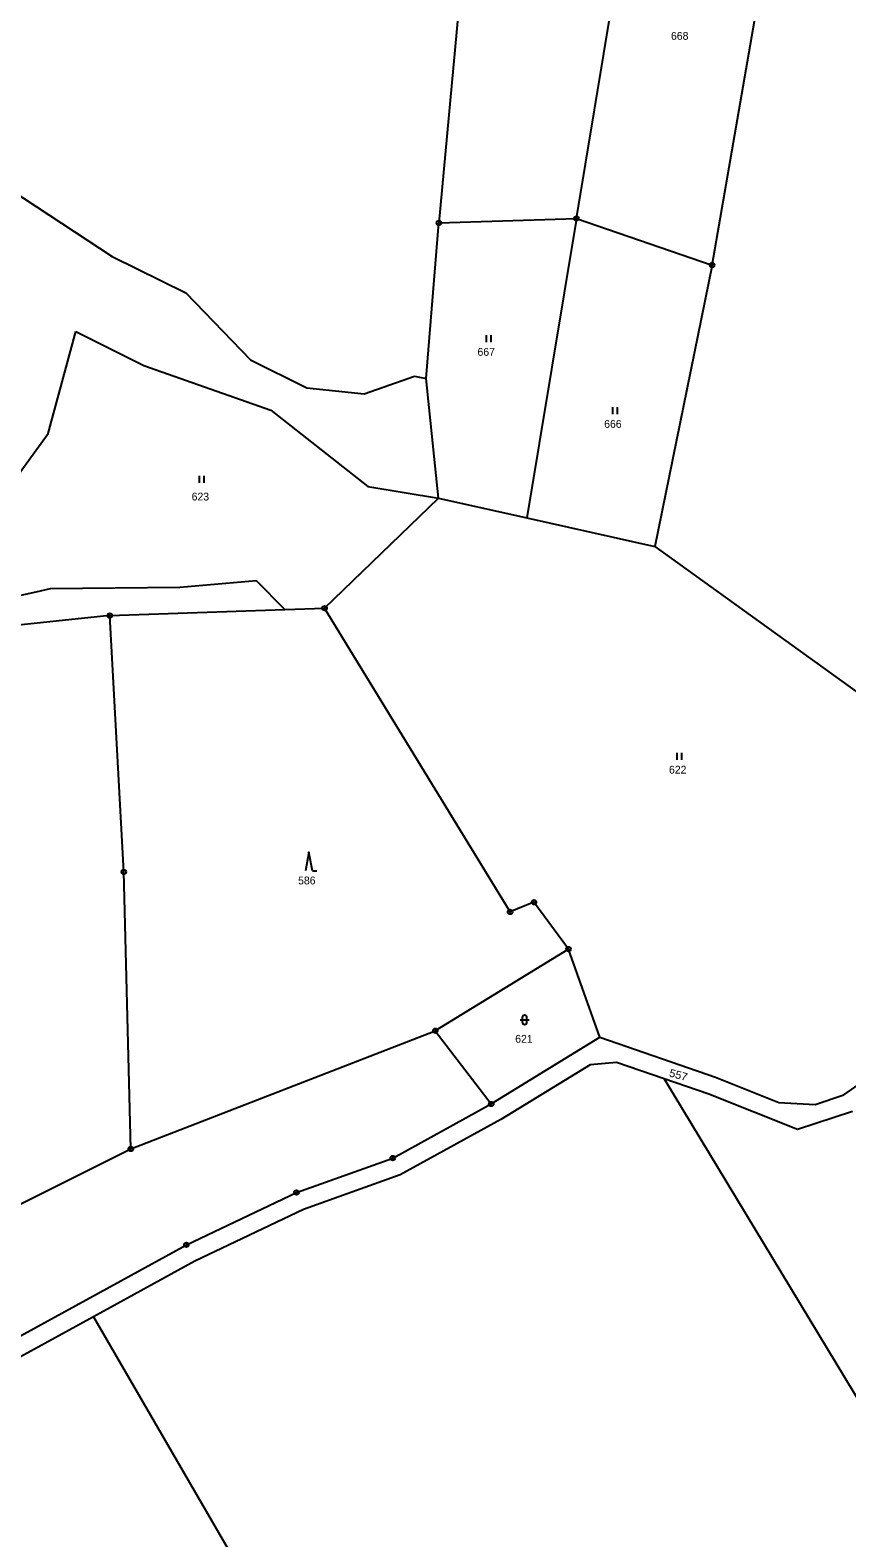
# Model space of a CAD drawing. Extents: x -719614 to -717765, y -1095834 to -1093862.
# Drawn here: x -718549.9 to -718372.3, y -1095029.2 to -1094701.4 of the extents above; entities that cross this region are included whole.
import ezdxf
from ezdxf.enums import TextEntityAlignment as Align

# ---------------------------------------------------------------- set-up
doc = ezdxf.new("R2010")
doc.units = 0
doc.header["$LTSCALE"] = 0.68
for name, color, linetype, lineweight in [('1', 7, 'Continuous', 25), ('3', 7, 'Continuous', 25), ('8', 7, 'Continuous', 25)]:
    doc.layers.add(name, color=color, linetype=linetype, lineweight=lineweight)
doc.layers.add('2', color=7, linetype='Continuous')

msp = doc.modelspace()

# ---------------------------------------------------------------- linework, layer by layer
at = {"layer": '1'}
for p, q in [((-718451.67, -1094641.63), (-718460.98, -1094743.29)), ((-718401.57, -1094752.45), (-718386.43, -1094665.2)), ((-718431.06, -1094742.32), (-718423.14, -1094694.58)), ((-718556.9, -1094734.3), (-718532.04, -1094750.61)), ((-718460.98, -1094743.29), (-718431.06, -1094742.32)), ((-718431.06, -1094742.32), (-718441.87, -1094807.45)), ((-718431.06, -1094742.32), (-718401.57, -1094752.45)), ((-718463.78, -1094777.11), (-718460.98, -1094743.29)), ((-718532.04, -1094750.61), (-718516.03, -1094758.47)), ((-718401.57, -1094752.45), (-718414, -1094813.69)), ((-718516.03, -1094758.47), (-718501.96, -1094773.06)), ((-718545.93, -1094789.06), (-718539.91, -1094766.88)), ((-718539.91, -1094766.88), (-718525.16, -1094774.33)), ((-718525.16, -1094774.33), (-718497.54, -1094783.98)), ((-718501.96, -1094773.06), (-718489.69, -1094779.16)), ((-718477.25, -1094780.47), (-718466.33, -1094776.59)), ((-718466.33, -1094776.59), (-718463.78, -1094777.11)), ((-718461.06, -1094803.16), (-718463.78, -1094777.11)), ((-718489.69, -1094779.16), (-718477.25, -1094780.47)), ((-718497.54, -1094783.98), (-718476.43, -1094800.59)), ((-718561.31, -1094810.12), (-718545.93, -1094789.06)), ((-718476.43, -1094800.59), (-718461.06, -1094803.16)), ((-718485.85, -1094827.06), (-718461.06, -1094803.16)), ((-718461.06, -1094803.16), (-718441.87, -1094807.45)), ((-718441.87, -1094807.45), (-718414, -1094813.69)), ((-718414, -1094813.69), (-718370.26, -1094845.2)), ((-718548.67, -1094823.59), (-718557.52, -1094825.53)), ((-718545.54, -1094822.9), (-718548.67, -1094823.59)), ((-718517.36, -1094822.59), (-718545.54, -1094822.9)), ((-718500.69, -1094821.11), (-718517.36, -1094822.59)), ((-718494.51, -1094827.36), (-718500.69, -1094821.11)), ((-718532.55, -1094828.68), (-718494.51, -1094827.36)), ((-718494.51, -1094827.36), (-718485.85, -1094827.06)), ((-718445.51, -1094893.13), (-718485.85, -1094827.06)), ((-718532.55, -1094828.68), (-718569.7, -1094832.59)), ((-718529.51, -1094884.42), (-718532.55, -1094828.68)), ((-718528, -1094944.67), (-718529.51, -1094884.42)), ((-718440.31, -1094891.02), (-718445.51, -1094893.13)), ((-718432.8, -1094901.2), (-718440.31, -1094891.02)), ((-718432.8, -1094901.2), (-718461.77, -1094918.96)), ((-718425.98, -1094920.36), (-718432.8, -1094901.2)), ((-718372.9, -1094932.91), (-718331.65, -1094903.88)), ((-718528, -1094944.67), (-718461.77, -1094918.96)), ((-718461.77, -1094918.96), (-718449.61, -1094934.89)), ((-718449.61, -1094934.89), (-718425.98, -1094920.36)), ((-718425.98, -1094920.36), (-718400.86, -1094929.03)), ((-718422.36, -1094925.84), (-718428.13, -1094926.38)), ((-718411.97, -1094929.43), (-718422.36, -1094925.84)), ((-718428.13, -1094926.38), (-718433.56, -1094929.72)), ((-718400.86, -1094929.03), (-718387.07, -1094934.54)), ((-718433.56, -1094929.72), (-718447.51, -1094938.3)), ((-718402.26, -1094932.78), (-718411.97, -1094929.43)), ((-718411.97, -1094929.43), (-718310.27, -1095097.96)), ((-718471.03, -1094946.65), (-718449.61, -1094934.89)), ((-718383.03, -1094940.46), (-718402.26, -1094932.78)), ((-718387.07, -1094934.54), (-718379.17, -1094934.98)), ((-718379.17, -1094934.98), (-718372.9, -1094932.91)), ((-718447.51, -1094938.3), (-718469.38, -1094950.31)), ((-718371.08, -1094936.52), (-718383.03, -1094940.46)), ((-718588.3, -1094974.71), (-718528, -1094944.67)), ((-718491.95, -1094954.14), (-718471.03, -1094946.65)), ((-718469.38, -1094950.31), (-718490.44, -1094957.85)), ((-718515.91, -1094965.53), (-718491.95, -1094954.14)), ((-718490.44, -1094957.85), (-718514.09, -1094969.09)), ((-718600.21, -1095011.66), (-718515.91, -1094965.53)), ((-718514.09, -1094969.09), (-718536.12, -1094981.15)), ((-718536.12, -1094981.15), (-718598.59, -1095015.34)), ((-718536.12, -1094981.15), (-718446.03, -1095136.65))]:
    msp.add_line(p, q, dxfattribs=at)
at = {"layer": '3'}
for p, q in [((-718450.651, -1094769.2), (-718450.651, -1094767.7)), ((-718449.65, -1094769.2), (-718449.65, -1094767.7)), ((-718423.131, -1094784.87), (-718423.131, -1094783.37)), ((-718422.13, -1094784.87), (-718422.13, -1094783.37)), ((-718513.031, -1094799.82), (-718513.031, -1094798.32)), ((-718512.03, -1094799.82), (-718512.03, -1094798.32)), ((-718409.171, -1094860.06), (-718409.171, -1094858.56)), ((-718408.17, -1094860.06), (-718408.17, -1094858.56)), ((-718488.5, -1094884.16), (-718487.504, -1094884.16)), ((-718442.851, -1094916.081), (-718442.851, -1094917.082)), ((-718441.849, -1094917.082), (-718441.849, -1094916.081)), ((-718443.351, -1094916.581), (-718441.349, -1094916.581))]:
    msp.add_line(p, q, dxfattribs=at)
msp.add_lwpolyline([(-718488.5, -1094884.16), (-718489.25, -1094880.16), (-718490, -1094884.16)], dxfattribs=at)
for centre, start, end in [((-718442.35, -1094916.0809), 0, 180), ((-718442.35, -1094917.0809), 180, 359.98789)]:
    msp.add_arc(centre, 0.5, start, end, dxfattribs=at)
at = {"layer": '8'}
for centre, radius in [((-718431.06, -1094742.3199), 0.5), ((-718431.06, -1094742.3199), 0.0303), ((-718460.98, -1094743.2899), 0.5), ((-718460.98, -1094743.2899), 0.0303), ((-718401.57, -1094752.4499), 0.5), ((-718401.57, -1094752.4499), 0.0303), ((-718485.85, -1094827.0599), 0.5), ((-718485.85, -1094827.0599), 0.0303), ((-718532.55, -1094828.6799), 0.5), ((-718532.55, -1094828.6799), 0.0303), ((-718529.51, -1094884.4199), 0.5), ((-718529.51, -1094884.4199), 0.0303), ((-718445.51, -1094893.1299), 0.5), ((-718445.51, -1094893.1299), 0.0303), ((-718440.31, -1094891.0199), 0.5), ((-718440.31, -1094891.0199), 0.0303), ((-718432.8, -1094901.1999), 0.5), ((-718432.8, -1094901.1999), 0.0303), ((-718461.77, -1094918.9599), 0.5), ((-718461.77, -1094918.9599), 0.0303), ((-718449.61, -1094934.8899), 0.5), ((-718449.61, -1094934.8899), 0.0303), ((-718528, -1094944.6699), 0.5), ((-718528, -1094944.6699), 0.0303), ((-718471.03, -1094946.6499), 0.5), ((-718471.03, -1094946.6499), 0.0303), ((-718491.95, -1094954.1399), 0.5), ((-718491.95, -1094954.1399), 0.0303), ((-718515.91, -1094965.5299), 0.5), ((-718515.91, -1094965.5299), 0.0303)]:
    msp.add_circle(centre, radius, dxfattribs=at)

# ---------------------------------------------------------------- texts
at = {"layer": '2'}
for s, p in [('668', (-718408.619, -1094703.462)), ('667', (-718450.699, -1094772.182)), ('666', (-718423.149, -1094787.852)), ('623', (-718512.859, -1094803.652)), ('622', (-718409.059, -1094863.042)), ('586', (-718489.709, -1094887.142)), ('621', (-718442.499, -1094921.572))]:
    msp.add_text(s, height=1.7, dxfattribs=at).set_placement(p, align=Align.CENTER)
at = {"layer": '2', "width": 1.05}
msp.add_text('557', height=1.7, rotation=345, dxfattribs=at).set_placement((-718409.11, -1094929.3983), align=Align.CENTER)

doc.saveas('drawing.dxf')
